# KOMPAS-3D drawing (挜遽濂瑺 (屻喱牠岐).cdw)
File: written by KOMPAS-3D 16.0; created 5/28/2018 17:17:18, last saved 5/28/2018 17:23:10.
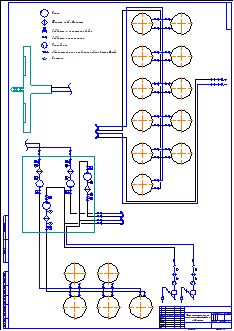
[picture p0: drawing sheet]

Sheet 1: A1, portrait

Title block, sheet 1: name: Технологическая схема / перевалочной нефтебазы / г. Мурманск; sheets: 1; sheet format: A1; stored path: C:\Users\Roman Ushak\Desktop\КР Вариант 21\ТС (Мурманск).cdw

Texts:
  Насос
  Фильтр грубой чистки
  Задвижка с электроприводом
  Задвижка механическая
  Расходомер
  Автоматическое сливно-наливное устройство
  Вентиль
  K5LT_THIN_RGB_0_0_0_THICK_0.18
  K5LT_AXLED_RGB_255_128_0_SC_1_THICK_0.18
Dimensions and other numbers on the sheet: 1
